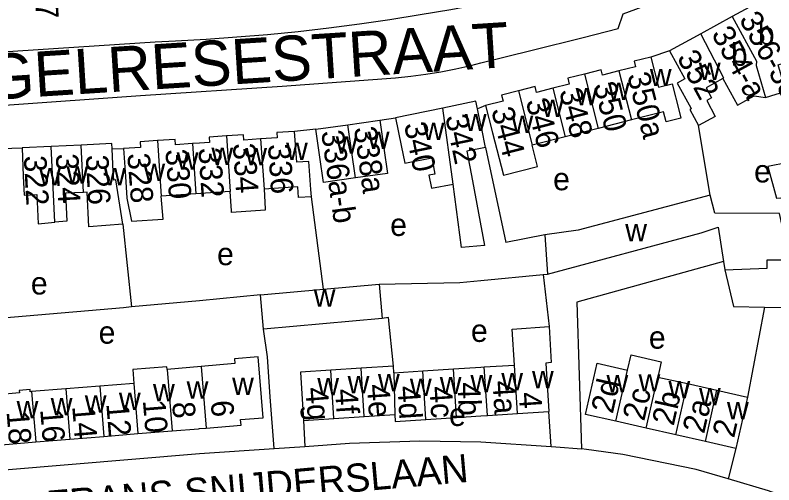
# Model space of a CAD drawing. Extents: x 163012 to 165277, y 382513 to 383987.
# Drawn here: x 163267.3 to 163402, y 383543.8 to 383627.2 of the extents above; entities that cross this region are included whole.
import ezdxf

# ---------------------------------------------------------------- set-up
doc = ezdxf.new("R2010")
doc.units = 0
for name, color, linetype in [('BLT_Basislijn', 7, 'Continuous'), ('BLT_Bebouwing', 7, 'Continuous'), ('BLT_Centroide', 7, 'Continuous'), ('BLT_Huisnummer', 7, 'Continuous'), ('BLT_Huisnummer_ tussenligend', 7, 'Continuous'), ('BLT_Huisnummer_reeks', 7, 'Continuous'), ('BLT_Onderverdeling_panden', 7, 'Continuous'), ('BLT_Straatnaam', 7, 'Continuous'), ('BLT_Straatnaam_hoofdweg', 7, 'Continuous')]:
    doc.layers.add(name, color=color, linetype=linetype)

msp = doc.modelspace()

# ---------------------------------------------------------------- linework, layer by layer
at = {"layer": 'BLT_Basislijn'}
for p, q in [((163292.17, 383622.44), (163242.12, 383619.08)), ((163383.45, 383620.87), (163380.16, 383619.78)), ((163350, 383610.85), (163349.39, 383610.61)), ((163350.82, 383611.18), (163350, 383610.85)), ((163332.08, 383608.58), (163334.83, 383608.96)), ((163390.69, 383595.23), (163388.6, 383607.61)), ((163320.71, 383606.97), (163316.94, 383606.58)), ((163264.92, 383603.53), (163268.55, 383603.66)), ((163284.55, 383603.48), (163286.58, 383603.54)), ((163322.05, 383578.58), (163319.9, 383594.97)), ((163286.44, 383590.09), (163288, 383575.41)), ((163361.36, 383588.2), (163354.44, 383586.88)), ((163350, 383580.11), (163361.04, 383581.2)), ((163361.04, 383581.2), (163361.79, 383581.21)), ((163361.04, 383581.2), (163362.08, 383571.92)), ((163331.92, 383579.45), (163346.24, 383579.74)), ((163346.24, 383579.74), (163350, 383580.11)), ((163400.32, 383575.36), (163397.3, 383559.41)), ((163400.32, 383575.36), (163410.8, 383575.24)), ((163362.48, 383550.63), (163362.07, 383556.87)), ((163318.53, 383555.27), (163318.77, 383550.67)), ((163350, 383551.46), (163362.48, 383550.63)), ((163313.3, 383550.28), (163318.77, 383550.67)), ((163395.25, 383550.32), (163393.86, 383544.89))]:
    msp.add_line(p, q, dxfattribs=at)
for points in [[(163359.07, 383620.99), (163368.14, 383623.26), (163374.34, 383624.82), (163375.27, 383627.45), (163385.2, 383631.18), (163394.04, 383635.21), (163408, 383643), (163411.11, 383644.02), (163414.54, 383644.24)], [(163350, 383629.19), (163344.63, 383628.17), (163339.24, 383627.24), (163333.84, 383626.38), (163328.43, 383625.6), (163323.01, 383624.9), (163317.58, 383624.28), (163312.13, 383623.74), (163306.69, 383623.28), (163301.23, 383622.9), (163295.77, 383622.6), (163292.17, 383622.44)], [(163350, 383618.72), (163359.07, 383620.99)], [(163334.86, 383616.1), (163337.55, 383616.38), (163340.24, 383616.73), (163342.91, 383617.17), (163345.57, 383617.68), (163348.21, 383618.27), (163350, 383618.72)], [(163265.52, 383611.25), (163289.56, 383612.93), (163314.73, 383614.61), (163334.86, 383616.1)], [(163350.82, 383603.73), (163354.44, 383586.88)], [(163393.03, 383583.46), (163367.04, 383576.29), (163367.83, 383550.21)], [(163393.29, 383582.03), (163394.82, 383575.49), (163400.32, 383575.36)], [(163310.85, 383577.59), (163300.05, 383576.52), (163288, 383575.41)], [(163288, 383575.41), (163286.58, 383575.27), (163254.01, 383572.46)], [(163334.47, 383564.9), (163333.62, 383573.52), (163332.46, 383573.34)], [(163313.3, 383550.28), (163312.58, 383559.45), (163312.13, 383566.57), (163311.39, 383571.48)], [(163318.77, 383550.67), (163326.66, 383551.23), (163339.15, 383551.67), (163350, 383551.46)], [(163228.67, 383543.09), (163230.79, 383543.58), (163300.04, 383549.39), (163313.3, 383550.28)], [(163362.48, 383550.63), (163363.29, 383550.58), (163367.83, 383550.21)], [(163393.86, 383544.89), (163388.22, 383546.57), (163375.18, 383549.21), (163368.74, 383550.14), (163367.83, 383550.21)], [(163416.42, 383536.6), (163405.04, 383541.31), (163401.01, 383542.76), (163393.86, 383544.89)]]:
    msp.add_lwpolyline(points, dxfattribs=at)
at = {"layer": 'BLT_Bebouwing'}
for p, q in [((163406.88, 383633.67), (163394.6, 383626.96)), ((163394.6, 383626.96), (163389.01, 383623.91)), ((163389.01, 383623.91), (163383.45, 383620.87)), ((163343.21, 383610.69), (163334.83, 383608.96)), ((163350, 383607.66), (163349.39, 383610.61)), ((163320.71, 383606.97), (163326.39, 383607.77)), ((163326.39, 383607.77), (163328.82, 383608.12)), ((163328.82, 383608.12), (163332.08, 383608.58)), ((163376.71, 383608.62), (163370.82, 383607.11)), ((163370.82, 383607.11), (163364.97, 383605.62)), ((163364.97, 383605.62), (163359.1, 383604.12)), ((163273.72, 383603.9), (163268.55, 383603.66)), ((163279.07, 383604.15), (163273.72, 383603.9)), ((163289.57, 383603.74), (163286.58, 383603.54)), ((163350.82, 383603.73), (163347.48, 383603.07)), ((163299.41, 383595.52), (163293.27, 383595.11)), ((163392.13, 383589.59), (163393.03, 383583.46)), ((163361.36, 383588.2), (163361.79, 383581.21)), ((163393.03, 383583.46), (163393.29, 383582.03)), ((163322.05, 383578.58), (163331.92, 383579.45)), ((163331.92, 383579.45), (163332.46, 383573.34)), ((163310.85, 383577.59), (163322.05, 383578.58)), ((163311.39, 383571.48), (163310.85, 383577.59)), ((163332.46, 383573.34), (163311.39, 383571.48)), ((163328.75, 383564.53), (163323.37, 383564.19)), ((163334.47, 383564.9), (163328.75, 383564.53)), ((163334.55, 383563.73), (163334.47, 383564.9)), ((163339.67, 383564.06), (163345.14, 383564.41)), ((163345.14, 383564.41), (163350, 383564.72)), ((163350, 383564.72), (163350.6, 383564.76)), ((163350.6, 383564.76), (163355.94, 383565.1)), ((163334.55, 383563.73), (163339.67, 383564.06)), ((163381.38, 383562.96), (163386.65, 383561.82)), ((163391.89, 383560.63), (163397.3, 383559.41)), ((163397.3, 383559.41), (163395.25, 383550.32)), ((163329.3, 383555.97), (163334.69, 383556.31)), ((163351.15, 383556.17), (163356.49, 383556.51)), ((163356.49, 383556.51), (163362.07, 383556.87)), ((163318.53, 383555.27), (163323.92, 383555.62)), ((163323.92, 383555.62), (163329.3, 383555.97)), ((163340.23, 383555.46), (163345.69, 383555.82)), ((163345.69, 383555.82), (163350, 383556.09)), ((163350, 383556.09), (163351.15, 383556.17)), ((163379.31, 383553.92), (163373.95, 383555.12)), ((163295.18, 383553.43), (163299.85, 383553.81)), ((163384.61, 383552.71), (163379.31, 383553.92)), ((163277.03, 383551.96), (163283.08, 383552.45)), ((163283.08, 383552.45), (163289.13, 383552.94)), ((163289.13, 383552.94), (163295.18, 383553.43)), ((163389.86, 383551.53), (163384.61, 383552.71)), ((163264.93, 383550.97), (163270.98, 383551.46)), ((163270.98, 383551.46), (163277.03, 383551.96)), ((163395.25, 383550.32), (163389.86, 383551.53))]:
    msp.add_line(p, q, dxfattribs=at)
for points in [[(163380.16, 383619.78), (163377.17, 383619.02), (163377.42, 383618.04), (163374.49, 383617.3)], [(163380.16, 383619.78), (163381.53, 383614.42), (163383.93, 383615.03), (163385.16, 383610.19), (163385.48, 383608.95), (163382.89, 383608.29), (163382.43, 383610.08), (163376.71, 383608.62)], [(163383.45, 383620.87), (163386.18, 383615.88), (163384.85, 383615.15), (163387.24, 383610.76), (163387.34, 383610.6), (163387.05, 383610.44), (163388.6, 383607.61)], [(163400.52, 383612.57), (163404.13, 383613.74), (163402.78, 383618.4), (163406.37, 383619.49)], [(163374.49, 383617.3), (163371.56, 383616.55), (163371.32, 383617.51), (163368.36, 383616.75)], [(163368.36, 383616.75), (163365.4, 383616), (163365.66, 383614.98), (163362.77, 383614.24)], [(163392.94, 383615.97), (163389.95, 383614.33), (163390.94, 383612.52), (163390.07, 383612.05), (163391.6, 383609.24), (163388.6, 383607.61)], [(163392.94, 383615.97), (163395.52, 383611.26), (163398.49, 383612.89), (163400.52, 383612.57)], [(163362.77, 383614.24), (163359.88, 383613.5), (163359.62, 383614.52), (163356.64, 383613.75)], [(163356.64, 383613.75), (163353.65, 383612.99), (163353.92, 383611.97), (163350.82, 383611.18)], [(163349.39, 383610.61), (163349.12, 383611.92), (163343.21, 383610.69)], [(163350.82, 383611.18), (163352.06, 383606.32), (163353.99, 383598.8), (163360.04, 383600.35), (163359.1, 383604.12)], [(163334.83, 383608.96), (163335.85, 383604.06), (163336.5, 383600.92), (163341.31, 383601.86), (163341.82, 383599.01), (163340.76, 383598.83), (163341.22, 383596.48), (163345.05, 383597.19)], [(163332.08, 383608.58), (163332.79, 383603.63), (163333.42, 383599.12), (163327.73, 383598.32)], [(163350.82, 383603.73), (163350.13, 383607.02), (163350, 383607.66)], [(163316.94, 383606.58), (163313.8, 383606.37), (163313.86, 383605.45), (163310.9, 383605.25)], [(163319.9, 383594.97), (163319.81, 383596.25), (163319.48, 383601.24), (163317.31, 383601.1), (163316.94, 383606.58)], [(163327.73, 383598.32), (163322.03, 383597.52), (163321.42, 383602.01), (163320.71, 383606.97)], [(163292.61, 383604.96), (163289.5, 383604.75), (163289.57, 383603.74)], [(163295.78, 383604.22), (163295.71, 383605.17), (163292.61, 383604.96)], [(163304.83, 383605.77), (163301.79, 383605.57), (163301.85, 383604.62)], [(163307.93, 383605.05), (163307.87, 383605.98), (163304.83, 383605.77)], [(163310.9, 383605.25), (163307.93, 383605.05)], [(163423.61, 383605.6), (163419.06, 383604.15), (163419.18, 383602.5), (163413.21, 383601.68), (163413.38, 383599.16), (163404.95, 383598.59), (163404.55, 383601.05), (163400.92, 383600.36), (163402.46, 383594.74), (163410.89, 383595.38)], [(163268.55, 383603.66), (163268.78, 383598.66), (163268.95, 383595.25), (163271.16, 383595.35), (163271.4, 383590.2), (163274.37, 383590.45)], [(163284.55, 383603.48), (163284.51, 383604.41), (163279.07, 383604.15)], [(163286.44, 383590.09), (163285.23, 383597.96), (163284.86, 383597.92), (163284.74, 383599.42), (163284.55, 383603.48)], [(163286.58, 383603.54), (163286.91, 383598.57), (163287.17, 383594.7), (163288.01, 383590.62), (163293.6, 383590.99), (163293.27, 383595.11)], [(163298.81, 383604.42), (163295.78, 383604.22)], [(163301.85, 383604.62), (163300.05, 383604.5), (163298.81, 383604.42)], [(163347.48, 383603.07), (163348.48, 383597.82), (163350.66, 383586.35), (163346.53, 383585.95), (163345.05, 383597.19)], [(163319.9, 383594.97), (163317.64, 383594.82), (163317.52, 383596.73), (163311.5, 383596.33)], [(163279.47, 383595.75), (163276.27, 383595.6), (163276.51, 383590.63), (163274.37, 383590.45)], [(163286.44, 383590.09), (163280.43, 383589.66), (163280.14, 383595.79), (163279.47, 383595.75)], [(163305.49, 383595.92), (163299.41, 383595.52)], [(163311.5, 383596.33), (163311.73, 383592.85), (163311.73, 383592.59), (163305.76, 383592.19), (163305.72, 383592.45), (163305.49, 383595.92)], [(163390.69, 383595.23), (163367.23, 383589.04), (163361.36, 383588.2)], [(163393.29, 383582.03), (163400.82, 383582.33), (163400.82, 383583.8), (163404.96, 383583.8), (163404.07, 383587.16), (163402.99, 383592), (163391.5, 383592.04), (163390.69, 383595.23)], [(163361.79, 383581.21), (163389.08, 383588.6), (163392.13, 383589.59)], [(163355.94, 383565.1), (163355.52, 383571.5), (163362.08, 383571.92)], [(163362.08, 383571.92), (163362.49, 383565.53), (163361.52, 383565.46), (163362.07, 383556.87)], [(163301.23, 383553.92), (163307.43, 383554.43), (163307.35, 383555.43), (163311.35, 383555.75), (163310.47, 383566.58), (163306.26, 383566.23), (163306.33, 383565.35), (163300.34, 383564.84)], [(163376, 383564.22), (163376.69, 383566.89), (163382, 383565.67), (163381.38, 383562.96)], [(163294.3, 383564.33), (163294.26, 383564.79), (163288.21, 383564.3), (163288.41, 383561.84)], [(163300.34, 383564.84), (163294.3, 383564.33)], [(163373.95, 383555.12), (163368.58, 383556.33), (163370.63, 383565.43), (163376, 383564.22)], [(163323.37, 383564.19), (163317.98, 383563.84), (163318.53, 383555.27)], [(163288.41, 383561.84), (163282.36, 383561.33)], [(163386.65, 383561.82), (163391.89, 383560.63)], [(163270.25, 383560.38), (163270.01, 383560.36), (163269.98, 383560.76), (163268.06, 383560.61), (163268.1, 383560.15), (163264.21, 383559.84)], [(163276.3, 383560.88), (163270.25, 383560.38)], [(163282.36, 383561.33), (163276.3, 383560.88)], [(163334.69, 383556.31), (163334.77, 383555.11), (163340.23, 383555.46)], [(163299.85, 383553.81), (163300.04, 383553.83), (163301.23, 383553.92)]]:
    msp.add_lwpolyline(points, dxfattribs=at)
at = {"layer": 'BLT_Onderverdeling_panden'}
for p, q in [((163374.49, 383617.3), (163376.71, 383608.62)), ((163368.36, 383616.75), (163370.82, 383607.11)), ((163362.77, 383614.24), (163364.97, 383605.62)), ((163356.64, 383613.75), (163359.1, 383604.12)), ((163345.05, 383597.19), (163343.21, 383610.69)), ((163327.73, 383598.32), (163326.39, 383607.77)), ((163292.61, 383604.96), (163293.27, 383595.11)), ((163304.83, 383605.77), (163305.49, 383595.92)), ((163310.9, 383605.25), (163311.5, 383596.33)), ((163274.37, 383590.45), (163273.72, 383603.9)), ((163279.47, 383595.75), (163279.07, 383604.15)), ((163298.81, 383604.42), (163299.41, 383595.52)), ((163329.3, 383555.97), (163328.75, 383564.53)), ((163345.69, 383555.82), (163345.14, 383564.41)), ((163351.15, 383556.17), (163350.6, 383564.76)), ((163356.49, 383556.51), (163355.94, 383565.1)), ((163294.3, 383564.33), (163295.18, 383553.43)), ((163323.92, 383555.62), (163323.37, 383564.19)), ((163334.55, 383563.73), (163334.69, 383556.31)), ((163340.23, 383555.46), (163339.67, 383564.06)), ((163373.95, 383555.12), (163376, 383564.22)), ((163288.41, 383561.84), (163289.13, 383552.94)), ((163379.31, 383553.92), (163381.38, 383562.96)), ((163384.61, 383552.71), (163386.65, 383561.82)), ((163270.25, 383560.38), (163270.98, 383551.46)), ((163276.3, 383560.88), (163277.03, 383551.96)), ((163282.36, 383561.33), (163283.08, 383552.45)), ((163389.86, 383551.53), (163391.89, 383560.63))]:
    msp.add_line(p, q, dxfattribs=at)
for points in [[(163394.6, 383626.96), (163398.92, 383619.05), (163398.83, 383618.3), (163400.52, 383612.57)], [(163392.94, 383615.97), (163393.08, 383616.04), (163389.01, 383623.91)], [(163300.34, 383564.84), (163301.23, 383553.92)]]:
    msp.add_lwpolyline(points, dxfattribs=at)

# ---------------------------------------------------------------- texts
at = {"layer": 'BLT_Centroide'}
for s, p in [('b', (163399.14, 383621.93)), ('b', (163394.36, 383618.22)), ('w', (163388.67, 383615.69)), ('w', (163379.98, 383614.61)), ('w', (163366.8, 383611.22)), ('w', (163372.53, 383612.17)), ('w', (163360.8, 383609.16)), ('w', (163347.14, 383606.62)), ('w', (163355.42, 383606.3)), ('w', (163339.67, 383605.08)), ('w', (163329.91, 383603.45)), ('w', (163324.22, 383602.64)), ('w', (163302.16, 383600.64)), ('w', (163308.17, 383600.58)), ('w', (163315.41, 383601.53)), ('w', (163296, 383599.77)), ('w', (163290.09, 383597.77)), ('w', (163271.58, 383597.02)), ('w', (163276.44, 383597.33)), ('w', (163283.09, 383597.02)), ('e', (163398.48, 383597.52)), ('e', (163362.81, 383596.13)), ('e', (163333.89, 383588.02)), ('w', (163375.61, 383587.06)), ('e', (163303.17, 383582.83)), ('e', (163270.12, 383577.63)), ('w', (163320.32, 383575.47)), ('e', (163282.15, 383568.9)), ('e', (163348.23, 383569.21)), ('e', (163379.8, 383568.01)), ('w', (163326.34, 383560.08)), ('w', (163331.72, 383560.42)), ('w', (163348.14, 383560.28)), ('w', (163353.61, 383560.64)), ('w', (163359.06, 383561)), ('w', (163372.28, 383560.28)), ('w', (163377.97, 383560.41)), ('w', (163291.8, 383558.64)), ('w', (163297.77, 383559.14)), ('w', (163305.84, 383559.81)), ('w', (163320.95, 383559.73)), ('w', (163337.39, 383559.59)), ('w', (163342.69, 383559.94)), ('w', (163383.28, 383559.2)), ('w', (163388.7, 383557.98)), ('w', (163273.64, 383556.17)), ('w', (163279.69, 383556.67)), ('w', (163285.75, 383557.12)), ('w', (163267.59, 383555.66)), ('w', (163393.67, 383555.45)), ('e', (163344.34, 383554.29))]:
    msp.add_text(s, height=4, dxfattribs=at).set_placement(p)
at = {"layer": 'BLT_Huisnummer'}
for s, rotation, p in [('287', 273.4277, (163270.56, 383635.35)), ('352', 298.6378, (163384.7, 383619.68)), ('350a', 284.3264, (163375.92, 383616.56)), ('350', 284.3267, (163369.96, 383614.84)), ('344', 284.3297, (163351.79, 383610.38)), ('340', 281.7106, (163336.33, 383607.85)), ('338a', 278.0268, (163327.43, 383607.2)), ('332', 273.8179, (163299.85, 383603.59)), ('336', 273.82, (163312.19, 383604.25)), ('322', 273.0489, (163268.87, 383602.23)), ('326', 272.7167, (163279.88, 383602.37)), ('328', 274.5082, (163287.22, 383602.61)), ('4a', 273.6826, (163352.04, 383562.24)), ('2d', 77.2911, (163373.39, 383556.33)), ('4g', 274.4914, (163318.82, 383561.04)), ('4e', 273.6796, (163329.77, 383561.6)), ('4c', 273.6804, (163340.85, 383561.24)), ('2c', 77.2925, (163378.98, 383555.02)), ('4', 273.6826, (163356.71, 383560.21)), ('2b', 77.2911, (163384.2, 383554.18)), ('10', 274.6374, (163289.99, 383558.82)), ('6', 274.6535, (163302.03, 383558.71)), ('2a', 77.2925, (163389.61, 383552.78)), ('18', 274.644, (163265.8, 383556.82)), ('14', 274.649, (163277.45, 383557.78)), ('2', 77.2985, (163394.92, 383552.03))]:
    msp.add_text(s, height=4, rotation=rotation, dxfattribs=at).set_placement(p)
at = {"layer": 'BLT_Huisnummer_ tussenligend'}
for s, rotation, p in [('348', 284.3297, (163363.86, 383613.73)), ('346', 284.3297, (163357.93, 383611.96)), ('342', 281.7106, (163343.65, 383609.22)), ('334', 273.8179, (163305.96, 383604.4)), ('324', 272.7167, (163274.54, 383602.57)), ('330', 274.5082, (163293.98, 383603.31)), ('4b', 271.097, (163345.9, 383562.02)), ('4f', 273.6796, (163324.11, 383560.79)), ('4d', 273.68, (163335.18, 383561.3)), ('12', 274.6374, (163283.5, 383558.23)), ('8', 274.6535, (163295.19, 383558.46)), ('16', 274.649, (163271.77, 383557.2))]:
    msp.add_text(s, height=4, rotation=rotation, dxfattribs=at).set_placement(p)
at = {"layer": 'BLT_Huisnummer_reeks'}
for s, rotation, p in [('356-358', 298.9842, (163395.73, 383626.48)), ('354-a', 298.6639, (163390.82, 383623.9)), ('336a-b', 278.0268, (163321.63, 383606.54))]:
    msp.add_text(s, height=4, rotation=rotation, dxfattribs=at).set_placement(p)
at = {"layer": 'BLT_Straatnaam'}
msp.add_text('FRANS SNIJDERSLAAN', height=5, rotation=5.041, dxfattribs=at).set_placement((163273.18, 383537.78))
at = {"layer": 'BLT_Straatnaam_hoofdweg'}
msp.add_text('TONGELRESESTRAAT', height=8, rotation=3.617, dxfattribs=at).set_placement((163240.1, 383610.75))

doc.saveas('drawing.dxf')
